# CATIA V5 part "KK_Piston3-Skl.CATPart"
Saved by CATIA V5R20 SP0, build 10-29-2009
Part number: Piston3-Skl
Bounding box of the stored display mesh (mm): x 63.395 to 99.999, y -13.265 to 0.34, z 0 to 100
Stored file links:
  G:\Khaled_CFAO_2011\ST2M\ST2M_GR1\msallin\Khaled\Version_Finale\KK_Piston3-Skl.CATPart
  C:\Users\Mathieu\Desktop\Think Motion\JOUG-MELEE2.CATProduct
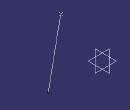
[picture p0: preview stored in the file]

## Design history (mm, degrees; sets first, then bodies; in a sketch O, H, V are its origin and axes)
External parameters (linked from other documents)
  `External.Taille du joug` = 100 mm
Set1
  Point1: linked copy from another document
  Point2: linked copy from another document
Set2
  Line1: type PtPt, FirstPoint Point1, SecondPoint Point2
  Point3: (0, 0, 0), relative to Point1
Body1 (main body)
